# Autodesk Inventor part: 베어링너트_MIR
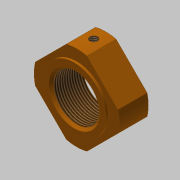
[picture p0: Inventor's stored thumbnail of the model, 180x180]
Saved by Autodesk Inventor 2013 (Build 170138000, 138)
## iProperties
Created: 2019-05
Part Number: 베어링너트_MIR
Material: 스테인리스강
Document SubType Name: Modeling
Designer: user
Density: 8.08 g/cm^3
Author: mduedu
d0: 35.000 mm
d1: 12.000 mm
d2: 0.00 deg
d3: 30.000 mm
d5: 30.000 mm
d7: 0.00 deg
d8: 26.000 mm
d9: 1.000 mm
d10: 0.00 deg
d20: 1.000 mm
d31: 5.000 mm
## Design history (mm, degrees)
derived "베어링너트.ipt"
  sketch "스케치1"
    geometry: C1 r 17.5 at (0, 0) reference; 1 further point
  sketch "스케치2"
    geometry: L1 (21.213, 0)-(0, 21.213) reference; L2 (0, 21.213)-(-21.213, 0) reference; L3 (-21.213, 0)-(0, -21.213) reference; L4 (0, -21.213)-(21.213, 0) reference; L5 (21.213, 0)-(-21.213, 0) reference; L6 (0, 21.213)-(0, -21.213) reference; 1 further point
  sketch "스케치3"
    geometry: C1 r 13 at (0, 0) reference; 1 further point
  sketch "스케치5"
    geometry: L1 (4.233, 0)-(-4.233, 0) reference; 3 further points
  node "작업 평면1"
feature "솔리드1::베어링너트.ipt"
tag "피쳐 태그1"
node "솔리드1"
other parameters: "d0" = 10, "d0_1" = 35, "d1" = 12, "d2" = 0 deg, "d3" = 30, "d5" = 30, "d7" = 0 deg, "d8" = 26, "d9" = 1, "d10" = 0 deg, "d20" = 1, "d31" = 5
